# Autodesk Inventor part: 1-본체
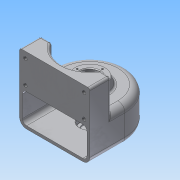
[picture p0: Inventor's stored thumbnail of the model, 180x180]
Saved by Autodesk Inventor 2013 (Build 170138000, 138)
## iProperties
Created: 2015-02
Part Number: 1-본체
Material: 알루미늄 6061
Document SubType Name: Modeling
Designer: Administrator
Density: 2.40731 g/cm^3
Mass: 511.028 g
Surface Area: 707.316 cm^2
Volume: 212.281 cm^3
Author: Administrator
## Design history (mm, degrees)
sketch "스케치1"
  geometry: L1 (-50, -50)-(50, -50); L2 (-50, 0)-(-50, -50); L3 (50, 0)-(50, -50); A1 r 50 centre (0, 0) between (-50, 0) and (50, 0); 1 further point
  constraints: 6 end point, 2 point on circle, 2 tangent, 1 centre point, 1 coincident, 1 horizontal, 1 parallel, 1 perpendicular
  dimensions: "d0" = 50 radius of A1; "d2" = 50 distance from line of L1 point (0, 0)
extrude "돌출1" new body sketch "스케치1" distance "d3" = 50; taper "d4" = 0 deg
feature "쉘1" dims "d5" = 4
fillet "모깎기1" dims "d10" = 10
node "작업 평면1"
sketch "스케치2"
  geometry: L1 (-40, -50)-(40, -50) reference; L2 (-40, -50)-(-50, -50) reference; L3 (50, -50)-(40, -50) reference; L4 (-50, -50)-(-50, -20); L5 (-50, -20)-(-34.641, -20); L6 (50, -50)-(50, -20); L7 (34.641, -20)-(50, -20); L8 (-50, -50)-(50, -50); A1 r 40 centre (0, 0) between (-34.641, -20) and (34.641, -20); 1 further point
  constraints: 10 end point, 4 perpendicular, 2 point on circle, 1 centre point, 1 coincident, 1 parallel
  dimensions: "d7" = 40 radius of A1; "d11" = 30 distance between parallel lines of L1 L5; "d12" = 30 distance between parallel lines of L1 L7
extrude "돌출2" join sketch "스케치2" stored distance "d13" = 86; taper "d14" = 0 deg
sketch "스케치3"
  geometry: C1 r 25 at (0, 0); A1 r 40 centre (0, 0) between (-34.641, -20) and (34.641, -20) reference; A2 r 40 centre (0, 0) between (40, 0) and (-40, 0) reference
  constraints: 2 coincident, 1 centre point
  dimensions: "d15" = 50 diameter of C1
extrude "돌출3" join sketch "스케치3" distance "d17" = 10; taper "d18" = -20 deg
sketch "스케치4"
  geometry: C1 r 20 at (0, 0); A1 r 40 centre (0, 0) between (40, 0) and (-40, 0) reference
  constraints: 1 centre point, 1 coincident
  dimensions: "d19" = 40 diameter of C1
extrude "돌출4" join sketch "스케치4" distance "d21" = 9; taper "d22" = 0 deg
hole "구멍1" diameter "d25" = 20; stored, may be unused: countersink angle "d29" = 90 deg, drill point angle "d31" = 118 deg; dims "d26" = 6, "d27" = 28, "d28" = 10, "d30" = 8, "d32" = 10, "d33" = 10
hole "구멍2" diameter "d36" = 20; stored, may be unused: countersink angle "d40" = 90 deg, drill point angle "d42" = 0 deg; dims "d34" = 10, "d35" = 10, "d37" = 6, "d38" = 28, "d39" = 8, "d41" = 10
sketch "스케치5"
  geometry: C1 r 14 at (0, 0) reference; C2 r 21.36 at (0, 0) reference; A1 r 18 centre (0, 0) between (0, 18) and (18, 0); 2 further points
  constraints: 4 point on circle, 2 horizontal alignment, 2 vertical alignment, 1 centre point, 1 coincident
  dimensions: "d43" = 36 diameter of A1
hole "구멍3" sketch "스케치5" at (0, 18), (18, 0), (-18, 0), (0, -18) diameter "d45" = 2.459; stored, may be unused: countersink angle "d49" = 90 deg, drill point angle "d51" = 118 deg; dims "d46" = 6, "d47" = 28, "d48" = 8, "d50" = 9
sketch "스케치6"
  geometry: L1 (0, 0)-(80, 0) reference; L2 (-10, 95)-(90, 95) reference; L3 (-1.75, 86)-(81.75, 86); L4 (81.75, 86)-(81.75, 53); L5 (81.75, 53)-(-1.75, 53); L6 (-1.75, 53)-(-1.75, 86); L7 (-1.75, 86)-(81.75, 53); L8 (81.75, 86)-(-1.75, 53); 8 further points
  constraints: 12 end point, 4 coincident, 4 midpoint, 2 parallel, 1 horizontal, 1 perpendicular, 1 vertical alignment
  dimensions: "d52" = 33 distance of L5.end L3.start; "d54" = 83.5 distance of L3.start L3.end; "d55" = 9 distance between parallel lines of L3 L2
hole "구멍4" sketch "스케치6" at (-1.75, 86), (81.75, 86), (81.75, 53), (-1.75, 53) diameter "d56" = 5.134; stored, may be unused: countersink angle "d60" = 90 deg, drill point angle "d62" = 118 deg; dims "d57" = 10, "d58" = 28, "d59" = 8, "d61" = 13
fillet "모깎기2" dims "d63" = 6, "d64" = 0.3, "d65" = 3
fillet "모깎기3" dims "d66" = 3
fillet "모깎기4" dims "d67" = 3
fillet "모깎기5" dims "d68" = 3
chamfer "모따기1" distance "d69" = 1; stored, may be unused: second distance "d70" = 2, angle "d71" = 45 deg
node "작업 평면2"
sketch "스케치7"
  geometry: L1 (40, 0)-(-40, 0) reference; 3 further points
  constraints: 1 midpoint, 1 vertical alignment, 1 other
  dimensions: "d72" = 25 distance from line of L1 point (0, 25)
feature "엠보싱1" sketch "스케치7" dims "d0" = 50, "d2" = 50, "d7" = 40, "d11" = 30, "d12" = 30, "d73" = 0.5, "d74" = 0
node "솔리드1"
other parameters: "d6" = 45
